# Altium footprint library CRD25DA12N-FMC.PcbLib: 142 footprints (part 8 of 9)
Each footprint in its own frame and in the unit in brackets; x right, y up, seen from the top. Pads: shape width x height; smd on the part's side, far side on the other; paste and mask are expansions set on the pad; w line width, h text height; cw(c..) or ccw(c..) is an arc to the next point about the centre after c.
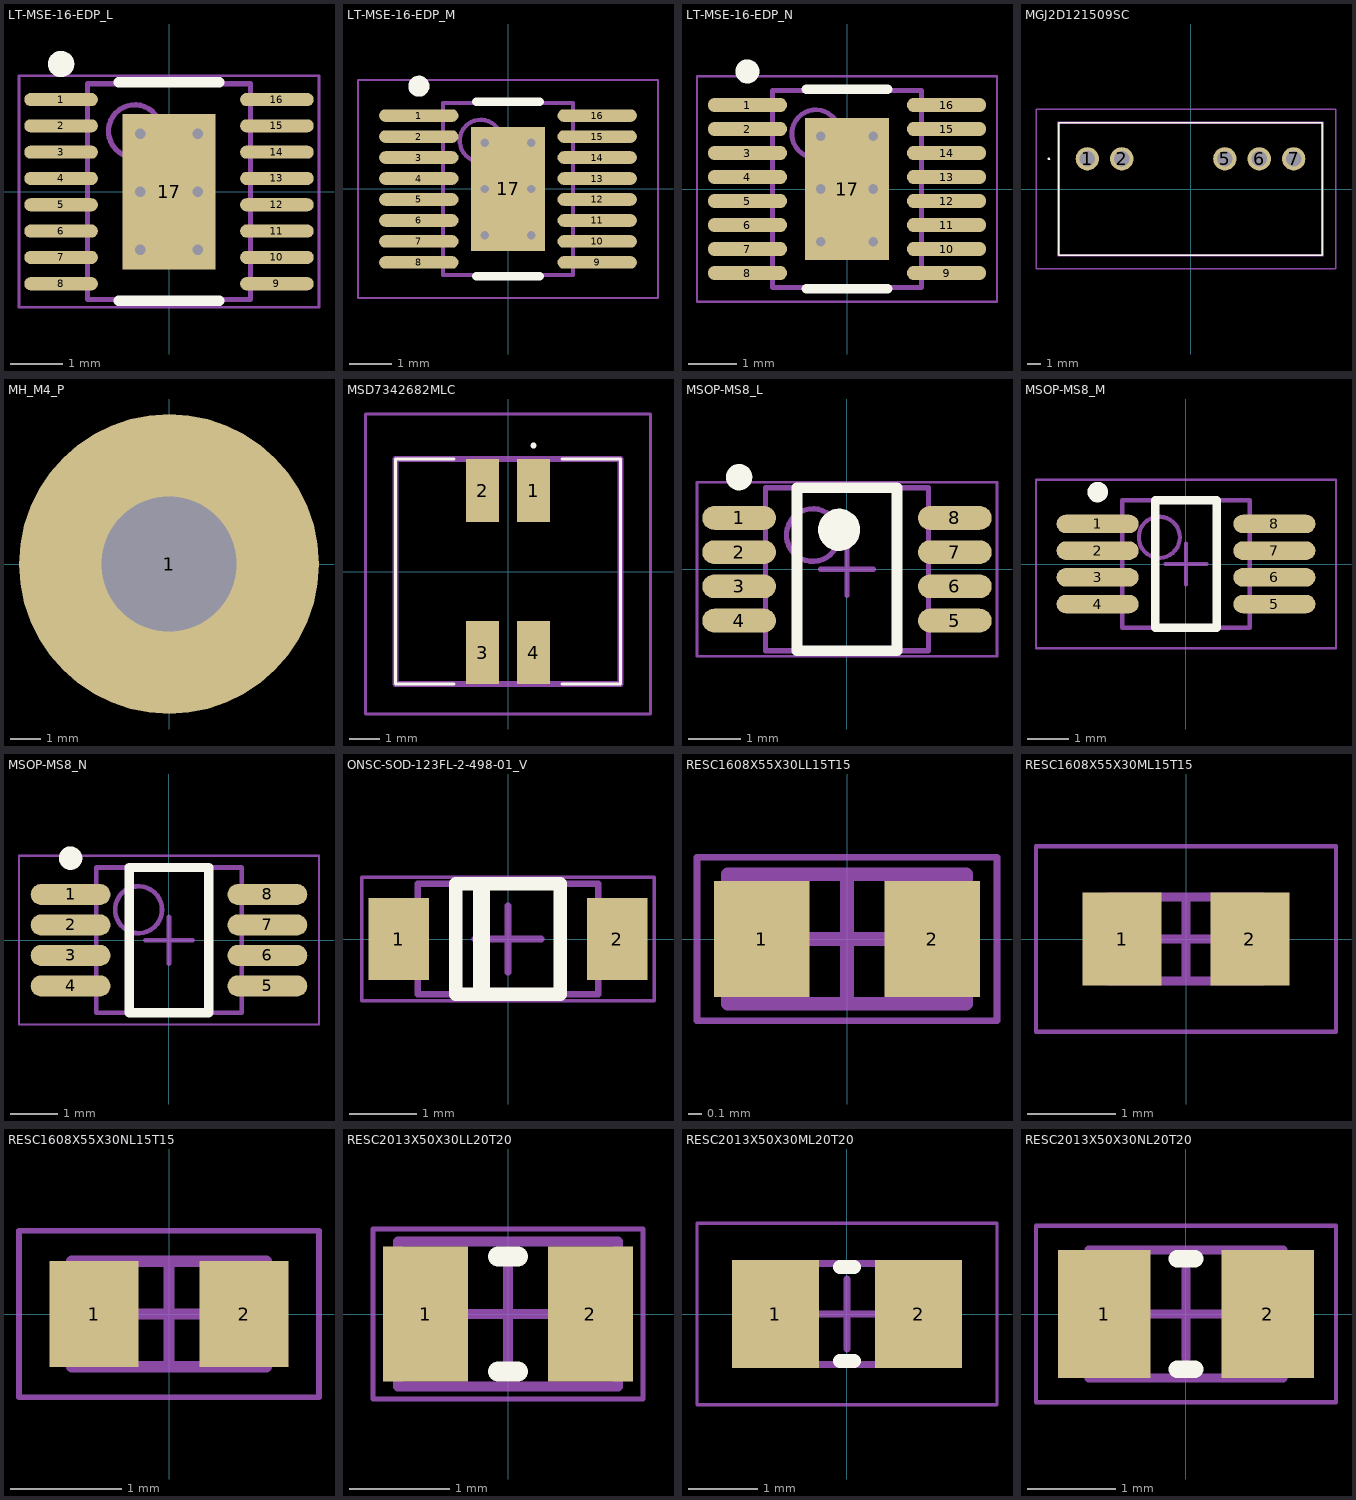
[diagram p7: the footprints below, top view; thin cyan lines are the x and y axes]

## LT-MSE-16-EDP_L [mm] "SOP, 16-Leads, Body 4.1x3.1mm, Pitch 0.5mm, Thermal Pad 2.95x1.76mm, IPC High Density"
height 1.1
pads (17):
  oval 1.4x0.25 smd: 1(-2.05,1.75) 2(-2.05,1.25) 3(-2.05,0.75) 4(-2.05,0.25) 5(-2.05,-0.25) 6(-2.05,-0.75) 7(-2.05,-1.25) 8(-2.05,-1.75) 9(2.05,-1.75) 10(2.05,-1.25) 11(2.05,-0.75) 12(2.05,-0.25) 13(2.05,0.25) 14(2.05,0.75) 15(2.05,1.25) 16(2.05,1.75)
  rect 1.76x2.95 smd: 17(0,0)
via 0.55,-1.1 diameter 0.5 hole 0.2
via -0.55,-1.1 diameter 0.5 hole 0.2
via 0.55,0 diameter 0.5 hole 0.2
via -0.55,0 diameter 0.5 hole 0.2
via 0.55,1.1 diameter 0.5 hole 0.2
via -0.55,1.1 diameter 0.5 hole 0.2
Top Overlay:
  circle w0.25: c-2.05,2.425 r0.125
  lines w0.2: -0.951,-2.075 0.951,-2.075 ; -0.951,2.075 0.951,2.075
Mechanical 13:
  circle w0.1: c-0.65,1.15 r0.5
  lines w0.1: -1.55,-2.05 1.55,-2.05 1.55,2.05 -1.55,2.05 -1.55,-2.05
Mechanical 15:
  lines w0.05: -2.85,-2.2 2.85,-2.2 2.85,2.2 -2.85,2.2 -2.85,-2.2
  lines w0.1: -0.5,0 0.5,0 ; 0,-0.5 0,0.5
3D body: height 1.1, standoff 0.05, extent -1.55,-2.05 1.55,2.05

## LT-MSE-16-EDP_M [mm] "SOP, 16-Leads, Body 4.1x3.1mm, Pitch 0.5mm, Thermal Pad 2.95x1.76mm, IPC Low Density"
height 1.1
pads (17):
  oval 1.89x0.3 smd: 1(-2.125,1.75) 2(-2.125,1.25) 3(-2.125,0.75) 4(-2.125,0.25) 5(-2.125,-0.25) 6(-2.125,-0.75) 7(-2.125,-1.25) 8(-2.125,-1.75) 9(2.125,-1.75) 10(2.125,-1.25) 11(2.125,-0.75) 12(2.125,-0.25) 13(2.125,0.25) 14(2.125,0.75) 15(2.125,1.25) 16(2.125,1.75)
  rect 1.76x2.95 smd: 17(0,0)
via -0.55,1.1 diameter 0.5 hole 0.2
via 0.55,1.1 diameter 0.5 hole 0.2
via -0.55,0 diameter 0.5 hole 0.2
via 0.55,0 diameter 0.5 hole 0.2
via -0.55,-1.1 diameter 0.5 hole 0.2
via 0.55,-1.1 diameter 0.5 hole 0.2
Top Overlay:
  circle w0.25: c-2.125,2.45 r0.125
  lines w0.2: -0.755,-2.075 0.755,-2.075 ; -0.755,2.075 0.755,2.075
Mechanical 13:
  circle w0.1: c-0.65,1.15 r0.5
  lines w0.1: -1.55,-2.05 1.55,-2.05 1.55,2.05 -1.55,2.05 -1.55,-2.05
Mechanical 15:
  lines w0.05: -3.575,-2.6 3.575,-2.6 3.575,2.6 -3.575,2.6 -3.575,-2.6
  lines w0.1: -0.5,0 0.5,0 ; 0,-0.5 0,0.5
3D body: height 1.1, standoff 0.05, extent -1.55,-2.05 1.55,2.05

## LT-MSE-16-EDP_N [mm] "SOP, 16-Leads, Body 4.1x3.1mm, Pitch 0.5mm, Thermal Pad 2.95x1.76mm, IPC Medium Density"
height 1.1
pads (17):
  oval 1.65x0.3 smd: 1(-2.075,1.75) 2(-2.075,1.25) 3(-2.075,0.75) 4(-2.075,0.25) 5(-2.075,-0.25) 6(-2.075,-0.75) 7(-2.075,-1.25) 8(-2.075,-1.75) 9(2.075,-1.75) 10(2.075,-1.25) 11(2.075,-0.75) 12(2.075,-0.25) 13(2.075,0.25) 14(2.075,0.75) 15(2.075,1.25) 16(2.075,1.75)
  rect 1.76x2.95 smd: 17(0,0)
via -0.55,1.1 diameter 0.5 hole 0.2
via 0.55,1.1 diameter 0.5 hole 0.2
via -0.55,0 diameter 0.5 hole 0.2
via 0.55,0 diameter 0.5 hole 0.2
via -0.55,-1.1 diameter 0.5 hole 0.2
via 0.55,-1.1 diameter 0.5 hole 0.2
Top Overlay:
  circle w0.25: c-2.075,2.45 r0.125
  lines w0.2: -0.851,-2.075 0.851,-2.075 ; -0.851,2.075 0.851,2.075
Mechanical 13:
  circle w0.1: c-0.65,1.15 r0.5
  lines w0.1: -1.55,-2.05 -1.55,2.05 1.55,2.05 1.55,-2.05 -1.55,-2.05
Mechanical 15:
  lines w0.05: -3.125,-2.35 -3.125,2.35 3.125,2.35 3.125,-2.35 -3.125,-2.35
  lines w0.1: -0.5,0 0.5,0 ; 0,-0.5 0,0.5
3D body: height 1.1, standoff 0.05, extent -1.55,-2.05 1.55,2.05

## MGJ2D121509SC [mm]
pads (5):
  round 1.725 hole 1.15: 1(-7.62,2.23) 2(-5.08,2.23) 5(2.54,2.23) 6(5.08,2.23) 7(7.62,2.23)
Top Overlay:
  lines w0.1: -10.52,2.23 cw(c-10.47,2.23) -10.42,2.23 cw(c-10.47,2.23) -10.52,2.23 ; -9.75,-4.9 9.75,-4.9 9.75,4.9 -9.75,4.9 -9.75,-4.9
Top Designator:
  text ".Designator" at 7.283,0.508 h1.52
Mechanical 13:
  lines w0.2: -9.75,-4.9 9.75,-4.9 9.75,4.9 -9.75,4.9 -9.75,-4.9
Mechanical 15:
  lines w0.1: -11.42,-5.9 10.75,-5.9 10.75,5.9 -11.42,5.9 -11.42,-5.9
3D body "MGJ2D121503SC.stp": height 13.09, standoff -3.51, extent -9.9,-5.09 9.6,4.73

## MH_M4_P [mm] "M4 plated mounting hole"
pads (1):
  round 10 hole 4.5: 1(0,0)
3D body "Extended Standoff (102mm).STEP": height -0.4, standoff -102.4, extent -4,-4.619 4,4.619

## MSD7342682MLC [mm]
pads (4):
  rect 1.1x2.1 smd: 1(0.85,2.7) 2(-0.85,2.7) 3(-0.85,-2.7) 4(0.85,-2.7)
Top Overlay:
  lines w0.1: -1.8,-3.75 -3.75,-3.75 -3.75,3.75 -1.8,3.75 ; 1.8,-3.75 3.75,-3.75 3.75,3.75 1.8,3.75 ; 0.8,4.2 cw(c0.85,4.2) 0.9,4.2 cw(c0.85,4.2) 0.8,4.2
Top Designator:
  text ".Designator" at 7.618,0.758 h1.52
Mechanical 13:
  lines w0.2: -3.75,-3.75 3.75,-3.75 3.75,3.75 -3.75,3.75 -3.75,-3.75
Mechanical 15:
  lines w0.1: -4.75,-4.75 4.75,-4.75 4.75,5.25 -4.75,5.25 -4.75,-4.75
3D body "MSD7342-682MLC.stp": height 4.7, standoff 0, extent -3.75,-3.75 3.75,3.75

## MSOP-MS8_L [mm] "TSOP, 8-Leads, Body 3x3mm, Pitch 0.65mm, IPC High Density"
height 1.1
pads (8):
  oval 1.4x0.45 smd: 1(-2.05,0.975) 2(-2.05,0.325) 3(-2.05,-0.325) 4(-2.05,-0.975) 5(2.05,-0.975) 6(2.05,-0.325) 7(2.05,0.325) 8(2.05,0.975)
Top Overlay:
  circle w0.4: c-0.15,0.75 r0.2
  circle w0.25: c-2.05,1.75 r0.125
  lines w0.2: -0.95,-1.55 0.95,-1.55 0.95,1.55 -0.95,1.55 -0.95,-1.55
Mechanical 13:
  circle w0.1: c-0.65,0.65 r0.5
  lines w0.1: -1.55,-1.55 1.55,-1.55 1.55,1.55 -1.55,1.55 -1.55,-1.55
Mechanical 15:
  lines w0.05: -2.85,-1.65 2.85,-1.65 2.85,1.65 -2.85,1.65 -2.85,-1.65
  lines w0.1: -0.5,0 0.5,0 ; 0,-0.5 0,0.5
3D body: height 1.1, standoff 0, extent -1.55,-1.55 1.55,1.55

## MSOP-MS8_M [mm] "TSOP, 8-Leads, Body 3x3mm, Pitch 0.65mm, IPC Low Density"
height 1.1
pads (8):
  oval 2x0.45 smd: 1(-2.15,0.975) 2(-2.15,0.325) 3(-2.15,-0.325) 4(-2.15,-0.975) 5(2.15,-0.975) 6(2.15,-0.325) 7(2.15,0.325) 8(2.15,0.975)
Top Overlay:
  circle w0.25: c-2.15,1.75 r0.125
  lines w0.2: -0.75,-1.55 -0.75,1.55 0.75,1.55 0.75,-1.55 -0.75,-1.55
Mechanical 13:
  circle w0.1: c-0.65,0.65 r0.5
  lines w0.1: -1.55,-1.55 -1.55,1.55 1.55,1.55 1.55,-1.55 -1.55,-1.55
Mechanical 15:
  lines w0.05: -3.65,-2.05 -3.65,2.05 3.65,2.05 3.65,-2.05 -3.65,-2.05
  lines w0.1: -0.5,0 0.5,0 ; 0,-0.5 0,0.5
3D body: height 1.1, standoff 0, extent -1.55,-1.55 1.55,1.55

## MSOP-MS8_N [mm] "TSOP, 8-Leads, Body 3x3mm, Pitch 0.65mm, IPC Medium Density"
height 1.1
pads (8):
  oval 1.7x0.45 smd: 1(-2.1,0.975) 2(-2.1,0.325) 3(-2.1,-0.325) 4(-2.1,-0.975) 5(2.1,-0.975) 6(2.1,-0.325) 7(2.1,0.325) 8(2.1,0.975)
Top Overlay:
  circle w0.25: c-2.1,1.75 r0.125
  lines w0.2: -0.85,-1.55 0.85,-1.55 0.85,1.55 -0.85,1.55 -0.85,-1.55
Mechanical 13:
  circle w0.1: c-0.65,0.65 r0.5
  lines w0.1: -1.55,-1.55 1.55,-1.55 1.55,1.55 -1.55,1.55 -1.55,-1.55
Mechanical 15:
  lines w0.05: -3.2,-1.8 3.2,-1.8 3.2,1.8 -3.2,1.8 -3.2,-1.8
  lines w0.1: -0.5,0 0.5,0 ; 0,-0.5 0,0.5
3D body: height 1.1, standoff 0, extent -1.55,-1.55 1.55,1.55

## ONSC-SOD-123FL-2-498-01_V [mm] "SOD, 2-Leads, Body 2.7x1.65mm"
height 1
pads (2):
  rect 0.91x1.22 smd: 1(-1.635,0) 2(1.635,0)
Top Overlay:
  lines w0.2: -0.78,-0.825 0.78,-0.825 0.78,0.825 -0.78,0.825 -0.78,-0.825
  lines w0.254: -0.4,-0.78 -0.4,0.78
Mechanical 13:
  lines w0.1: -1.35,-0.825 1.35,-0.825 1.35,0.825 -1.35,0.825 -1.35,-0.825
Mechanical 15:
  lines w0.05: -2.19,-0.925 2.19,-0.925 2.19,0.925 -2.19,0.925 -2.19,-0.925
  lines w0.1: -0.5,0 0.5,0 ; 0,-0.5 0,0.5
3D body: height 1, standoff 0, extent -1.35,-0.825 1.35,0.825

## RESC1608X55X30LL15T15 [mm] "Chip Resistor, 2-Leads, Body 1.60x0.80mm, IPC High Density"
height 0.55
pads (2):
  rect 0.7x0.85 smd: 1(-0.625,0) 2(0.625,0)
Mechanical 13:
  lines w0.1: -0.875,-0.475 0.875,-0.475 0.875,0.475 -0.875,0.475 -0.875,-0.475
Mechanical 15:
  lines w0.05: -1.1,-0.6 1.1,-0.6 1.1,0.6 -1.1,0.6 -1.1,-0.6
  lines w0.1: -0.475,0 0.475,0 ; 0,-0.475 0,0.475
3D body: height 0.55, standoff 0, extent 0.575,-0.475 0.875,0.475
3D body: height 0.55, standoff 0, extent -0.875,-0.475 -0.575,0.475
3D body: height 0.55, standoff 0, extent -0.575,-0.475 0.575,0.475

## RESC1608X55X30ML15T15 [mm] "Chip Resistor, 2-Leads, Body 1.60x0.80mm, IPC Low Density"
height 0.55
pads (2):
  rect 0.9x1.05 smd: 1(-0.725,0) 2(0.725,0)
Mechanical 13:
  lines w0.1: -0.875,-0.475 0.875,-0.475 0.875,0.475 -0.875,0.475 -0.875,-0.475
Mechanical 15:
  lines w0.05: -1.7,-1.05 1.7,-1.05 1.7,1.05 -1.7,1.05 -1.7,-1.05
  lines w0.1: -0.475,0 0.475,0 ; 0,-0.475 0,0.475
3D body: height 0.55, standoff 0, extent 0.575,-0.475 0.875,0.475
3D body: height 0.55, standoff 0, extent -0.875,-0.475 -0.575,0.475
3D body: height 0.55, standoff 0, extent -0.575,-0.475 0.575,0.475

## RESC1608X55X30NL15T15 [mm] "Chip Resistor, 2-Leads, Body 1.60x0.80mm, IPC Medium Density"
height 0.55
pads (2):
  rect 0.8x0.95 smd: 1(-0.675,0) 2(0.675,0)
Mechanical 13:
  lines w0.1: -0.875,-0.475 0.875,-0.475 0.875,0.475 -0.875,0.475 -0.875,-0.475
Mechanical 15:
  lines w0.05: -1.35,-0.75 1.35,-0.75 1.35,0.75 -1.35,0.75 -1.35,-0.75
  lines w0.1: -0.475,0 0.475,0 ; 0,-0.475 0,0.475
3D body: height 0.55, standoff 0, extent 0.575,-0.475 0.875,0.475
3D body: height 0.55, standoff 0, extent -0.875,-0.475 -0.575,0.475
3D body: height 0.55, standoff 0, extent -0.575,-0.475 0.575,0.475

## RESC2013X50X30LL20T20 [mm] "Chip Resistor, 2-Leads, Body 2.00x1.25mm, IPC High Density"
height 0.5
pads (2):
  rect 0.85x1.35 smd: 1(-0.825,0) 2(0.825,0)
Top Overlay:
  lines w0.2: -0.1,-0.575 0.1,-0.575 ; -0.1,0.575 0.1,0.575
Mechanical 13:
  lines w0.1: -1.1,-0.725 1.1,-0.725 1.1,0.725 -1.1,0.725 -1.1,-0.725
Mechanical 15:
  lines w0.05: -1.35,-0.85 1.35,-0.85 1.35,0.85 -1.35,0.85 -1.35,-0.85
  lines w0.1: -0.5,0 0.5,0 ; 0,-0.5 0,0.5
3D body: height 0.5, standoff 0, extent 0.8,-0.725 1.1,0.725
3D body: height 0.5, standoff 0, extent -1.1,-0.725 -0.8,0.725
3D body: height 0.5, standoff 0, extent -0.8,-0.725 0.8,0.725

## RESC2013X50X30ML20T20 [mm] "Chip Resistor, 2-Leads, Body 2.00x1.25mm, IPC Low Density"
height 0.5
pads (2):
  rect 1.25x1.55 smd: 1(-1.025,0) 2(1.025,0)
Top Overlay:
  lines w0.2: -0.1,-0.675 0.1,-0.675 ; -0.1,0.675 0.1,0.675
Mechanical 13:
  lines w0.1: -1.1,-0.725 1.1,-0.725 1.1,0.725 -1.1,0.725 -1.1,-0.725
Mechanical 15:
  lines w0.05: -2.15,-1.3 2.15,-1.3 2.15,1.3 -2.15,1.3 -2.15,-1.3
  lines w0.1: -0.5,0 0.5,0 ; 0,-0.5 0,0.5
3D body: height 0.5, standoff 0, extent 0.8,-0.725 1.1,0.725
3D body: height 0.5, standoff 0, extent -1.1,-0.725 -0.8,0.725
3D body: height 0.5, standoff 0, extent -0.8,-0.725 0.8,0.725

## RESC2013X50X30NL20T20 [mm] "Chip Resistor, 2-Leads, Body 2.00x1.25mm, IPC Medium Density"
height 0.5
pads (2):
  rect 1.05x1.45 smd: 1(-0.925,0) 2(0.925,0)
Top Overlay:
  lines w0.2: -0.1,-0.625 0.1,-0.625 ; -0.1,0.625 0.1,0.625
Mechanical 13:
  lines w0.1: -1.1,-0.725 -1.1,0.725 1.1,0.725 1.1,-0.725 -1.1,-0.725
Mechanical 15:
  lines w0.05: -1.7,-1 -1.7,1 1.7,1 1.7,-1 -1.7,-1
  lines w0.1: -0.5,0 0.5,0 ; 0,-0.5 0,0.5
3D body: height 0.5, standoff 0, extent -0.8,-0.725 0.8,0.725
3D body: height 0.5, standoff 0, extent -1.1,-0.725 -0.8,0.725
3D body: height 0.5, standoff 0, extent 0.8,-0.725 1.1,0.725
